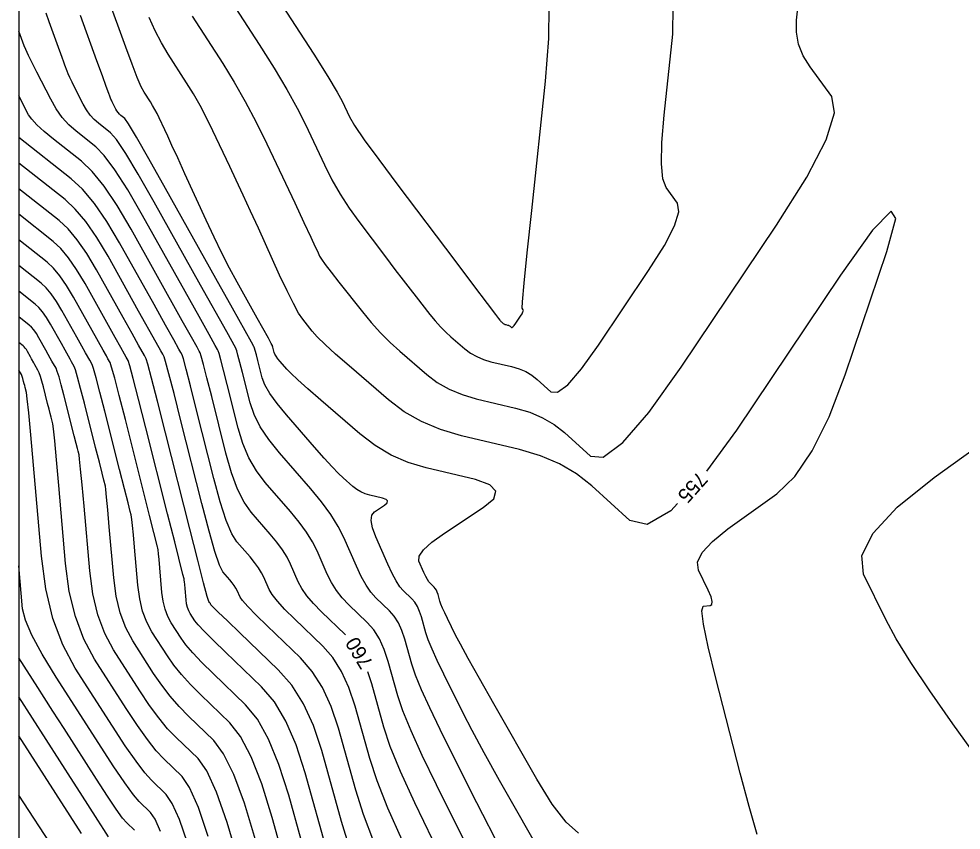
# Model space of a CAD drawing. Extents: x 2082232 to 2083549, y 592624 to 593832.
# Drawn here: x 2082231.79 to 2082277.24, y 593503.2 to 593542.34 of the extents above; entities that cross this region are included whole.
import ezdxf

# ---------------------------------------------------------------- set-up
doc = ezdxf.new("R2010")
doc.units = 0
for name, color, linetype in [('DT_X_Contour_Major', 7, 'Continuous'), ('DT_X_Contour_Minor', 7, 'Continuous'), ('DT_X_TIN_Hull', 7, 'Continuous')]:
    doc.layers.add(name, color=color, linetype=linetype)

msp = doc.modelspace()

# ---------------------------------------------------------------- linework, layer by layer
at = {"layer": 'DT_X_Contour_Major'}
for points in [[(2082263.563, 593518.955), (2082263.232, 593518.606), (2082262.096, 593517.946), (2082261.258, 593518.142), (2082259.42, 593519.808), (2082258.685, 593520.386), (2082257.861, 593520.87), (2082256.945, 593521.26), (2082255.94, 593521.556), (2082253.138, 593522.222), (2082252.129, 593522.518), (2082251.205, 593522.905), (2082250.366, 593523.383), (2082249.611, 593523.954), (2082247.711, 593525.597), (2082247.066, 593526.163), (2082246.556, 593526.63), (2082246.181, 593526.997), (2082245.941, 593527.265), (2082245.481, 593527.848), (2082245.282, 593528.145), (2082245.029, 593528.599), (2082244.724, 593529.21), (2082244.365, 593529.978), (2082243.338, 593532.235), (2082242.963, 593533.057), (2082242.609, 593533.827), (2082242.275, 593534.547), (2082241.961, 593535.216), (2082241.151, 593536.933), (2082240.844, 593537.561), (2082240.529, 593538.157), (2082240.207, 593538.722), (2082239.876, 593539.254), (2082238.986, 593540.633), (2082238.662, 593541.173), (2082238.357, 593541.762), (2082238.072, 593542.398)], [(2082247.544, 593512.615), (2082247.519, 593512.643), (2082246.388, 593513.73), (2082246, 593514.126), (2082245.682, 593514.501), (2082245.436, 593514.853), (2082245.261, 593515.183), (2082244.888, 593516.034), (2082244.722, 593516.363), (2082244.505, 593516.712), (2082244.235, 593517.082), (2082243.914, 593517.471), (2082242.989, 593518.536), (2082242.653, 593519.014), (2082242.339, 593519.647), (2082242.047, 593520.436), (2082241.778, 593521.382), (2082241.088, 593524.11), (2082240.859, 593525.01), (2082240.691, 593525.661), (2082240.582, 593526.065), (2082240.534, 593526.221), (2082240.487, 593526.306), (2082240.384, 593526.49), (2082240.112, 593526.977), (2082239.669, 593527.769), (2082237.199, 593532.19), (2082236.527, 593533.33), (2082235.903, 593534.258), (2082235.328, 593534.973), (2082234.801, 593535.475), (2082233.462, 593536.531), (2082233.01, 593536.902), (2082232.658, 593537.222), (2082232.407, 593537.493), (2082232.256, 593537.713), (2082231.787, 593538.625)], [(2082267.402, 593502.988), (2082267.006, 593504.338), (2082266.581, 593505.938), (2082265.409, 593510.536), (2082265.041, 593512.045), (2082264.814, 593513.127), (2082264.729, 593513.781), (2082264.787, 593514.006), (2082265.129, 593514.035), (2082265.219, 593514.089), (2082265.234, 593514.231), (2082265.172, 593514.459), (2082265.035, 593514.775), (2082264.569, 593515.731), (2082264.527, 593516.125), (2082264.75, 593516.589), (2082265.237, 593517.122), (2082265.99, 593517.725), (2082268.351, 593519.427), (2082269.221, 593520.264), (2082270.058, 593521.498), (2082270.863, 593523.131), (2082271.637, 593525.161), (2082273.657, 593531.106), (2082274.085, 593532.707), (2082273.853, 593533.05), (2082272.962, 593532.135), (2082271.412, 593529.963), (2082266.398, 593522.495), (2082264.957, 593520.521)], [(2082246.003, 593500.579), (2082244.802, 593504.885), (2082244.334, 593506.369), (2082243.832, 593507.59), (2082243.295, 593508.549), (2082242.724, 593509.246), (2082241.155, 593510.754), (2082240.617, 593511.284), (2082240.181, 593511.744), (2082239.847, 593512.133), (2082239.615, 593512.451), (2082239.132, 593513.206), (2082238.968, 593513.509), (2082238.84, 593513.853), (2082238.748, 593514.238), (2082238.691, 593514.663), (2082238.587, 593515.852), (2082238.552, 593516.246), (2082238.525, 593516.534), (2082238.506, 593516.717), (2082238.496, 593516.796), (2082238.478, 593516.864), (2082238.303, 593517.556), (2082238.095, 593518.381), (2082237.805, 593519.527), (2082236.925, 593523.008), (2082236.631, 593524.159), (2082236.41, 593525), (2082236.262, 593525.533), (2082236.187, 593525.757), (2082236.084, 593525.941), (2082236.008, 593526.077), (2082235.857, 593526.348), (2082235.328, 593527.294), (2082234.423, 593528.914), (2082234.089, 593529.474), (2082233.767, 593529.94), (2082233.456, 593530.313), (2082233.157, 593530.591), (2082231.787, 593531.671)], [(2082239.917, 593502.584), (2082239.529, 593503.709), (2082239.189, 593504.487), (2082238.897, 593504.919), (2082238.18, 593505.608), (2082237.861, 593505.965), (2082237.441, 593506.519), (2082236.921, 593507.271), (2082236.3, 593508.22), (2082234.51, 593511.014), (2082233.905, 593512.137), (2082233.431, 593513.411), (2082233.089, 593514.835), (2082232.879, 593516.41), (2082232.493, 593520.811), (2082232.363, 593522.267), (2082232.264, 593523.334), (2082232.195, 593524.012), (2082232.155, 593524.302), (2082232.091, 593524.556), (2082232.068, 593524.646), (2082232.049, 593524.724), (2082232.017, 593524.847), (2082231.984, 593524.981), (2082231.969, 593525.03), (2082231.952, 593525.079), (2082231.931, 593525.126), (2082231.907, 593525.173), (2082231.787, 593525.387)], [(2082251.757, 593502.716), (2082250.885, 593504.512), (2082250.2, 593506.019), (2082249.701, 593507.238), (2082249.389, 593508.167), (2082248.805, 593510.259), (2082248.616, 593510.83)], [(2082233.514, 593502.253), (2082231.787, 593504.889)]]:
    msp.add_lwpolyline(points, dxfattribs=at)
at = {"layer": 'DT_X_Contour_Minor'}
for points in [[(2082242.453, 593546.143), (2082245.118, 593542.018), (2082246.009, 593540.63), (2082246.683, 593539.557), (2082247.141, 593538.802), (2082247.382, 593538.362), (2082247.735, 593537.612), (2082247.98, 593537.195), (2082248.45, 593536.507), (2082249.145, 593535.547), (2082250.065, 593534.316), (2082252.817, 593530.672), (2082253.723, 593529.472), (2082254.377, 593528.606), (2082254.778, 593528.075), (2082254.928, 593527.878), (2082254.992, 593527.797), (2082255.015, 593527.769), (2082255.039, 593527.742), (2082255.063, 593527.718), (2082255.087, 593527.696), (2082255.151, 593527.641), (2082255.176, 593527.622), (2082255.204, 593527.606), (2082255.235, 593527.593), (2082255.269, 593527.583), (2082255.363, 593527.56), (2082255.397, 593527.551), (2082255.427, 593527.537), (2082255.455, 593527.521), (2082255.479, 593527.502), (2082255.541, 593527.446), (2082255.572, 593527.444), (2082255.618, 593527.478), (2082255.68, 593527.55), (2082255.758, 593527.658), (2082255.985, 593527.997), (2082256.057, 593528.111), (2082256.103, 593528.2), (2082256.123, 593528.265), (2082256.117, 593528.304), (2082256.065, 593528.374), (2082256.079, 593528.689), (2082256.16, 593529.581), (2082256.309, 593531.051), (2082256.524, 593533.097), (2082257.187, 593539.323), (2082257.355, 593541.393), (2082257.361, 593542.933)], [(2082241.298, 593544.307), (2082243.371, 593541.097), (2082244.094, 593539.953), (2082244.709, 593538.927), (2082245.215, 593538.021), (2082245.613, 593537.233), (2082246.529, 593535.291), (2082246.889, 593534.573), (2082247.285, 593533.878), (2082247.716, 593533.205), (2082248.182, 593532.554), (2082249.471, 593530.847), (2082249.925, 593530.247), (2082250.322, 593529.727), (2082250.661, 593529.287), (2082250.943, 593528.927), (2082251.616, 593528.074), (2082251.869, 593527.767), (2082252.122, 593527.485), (2082252.375, 593527.228), (2082252.628, 593526.996), (2082253.304, 593526.412), (2082253.573, 593526.209), (2082253.871, 593526.039), (2082254.2, 593525.901), (2082254.558, 593525.796), (2082255.555, 593525.559), (2082255.913, 593525.454), (2082256.238, 593525.315), (2082256.532, 593525.143), (2082256.793, 593524.937), (2082257.447, 593524.345), (2082257.774, 593524.319), (2082258.267, 593524.685), (2082258.924, 593525.444), (2082259.746, 593526.595), (2082262.158, 593530.188), (2082262.924, 593531.402), (2082263.413, 593532.35), (2082263.623, 593533.031), (2082263.557, 593533.445), (2082263.009, 593534.195), (2082262.849, 593534.624), (2082262.779, 593535.349), (2082262.799, 593536.371), (2082262.91, 593537.688), (2082263.326, 593541.595), (2082263.345, 593542.941)], [(2082240.142, 593542.47), (2082241.624, 593540.176), (2082242.173, 593539.289), (2082242.71, 593538.35), (2082243.234, 593537.357), (2082243.745, 593536.312), (2082245.092, 593533.455), (2082245.54, 593532.507), (2082245.871, 593531.803), (2082246.086, 593531.345), (2082246.185, 593531.132), (2082246.294, 593530.892), (2082246.383, 593530.746), (2082246.568, 593530.488), (2082246.848, 593530.119), (2082247.224, 593529.638), (2082248.355, 593528.206), (2082248.787, 593527.683), (2082249.233, 593527.191), (2082249.694, 593526.729), (2082250.169, 593526.296), (2082251.458, 593525.183), (2082251.969, 593524.796), (2082252.538, 593524.472), (2082253.164, 593524.209), (2082253.848, 593524.009), (2082255.747, 593523.558), (2082256.429, 593523.357), (2082257.049, 593523.092), (2082257.609, 593522.764), (2082258.106, 593522.373), (2082259.353, 593521.244), (2082259.977, 593521.194), (2082260.915, 593521.892), (2082262.168, 593523.339), (2082263.735, 593525.532), (2082268.332, 593532.38), (2082269.791, 593534.694), (2082270.722, 593536.499), (2082271.124, 593537.797), (2082270.997, 593538.587), (2082269.953, 593540.016), (2082269.618, 593540.559), (2082269.397, 593541.118), (2082269.29, 593541.691), (2082269.297, 593542.279), (2082269.466, 593543.867)], [(2082258.787, 593503.051), (2082258.179, 593503.589), (2082257.505, 593504.457), (2082256.764, 593505.655), (2082254.7, 593509.287), (2082254.004, 593510.516), (2082253.465, 593511.479), (2082253.082, 593512.176), (2082252.855, 593512.607), (2082252.461, 593513.401), (2082252.327, 593513.676), (2082252.222, 593513.907), (2082252.145, 593514.094), (2082252.097, 593514.237), (2082252.008, 593514.558), (2082251.97, 593514.671), (2082251.925, 593514.77), (2082251.872, 593514.854), (2082251.811, 593514.924), (2082251.637, 593515.09), (2082251.569, 593515.171), (2082251.494, 593515.287), (2082251.413, 593515.44), (2082251.326, 593515.628), (2082251.085, 593516.178), (2082251.094, 593516.417), (2082251.302, 593516.72), (2082251.708, 593517.087), (2082252.313, 593517.518), (2082254.19, 593518.755), (2082254.695, 593519.187), (2082254.8, 593519.556), (2082254.506, 593519.862), (2082253.813, 593520.106), (2082251.434, 593520.671), (2082250.565, 593520.933), (2082249.743, 593521.294), (2082248.967, 593521.755), (2082248.239, 593522.314), (2082246.36, 593523.939), (2082245.728, 593524.489), (2082245.242, 593524.923), (2082244.902, 593525.238), (2082244.708, 593525.437), (2082244.384, 593525.81), (2082244.275, 593525.942), (2082244.192, 593526.057), (2082244.135, 593526.156), (2082244.103, 593526.239), (2082244.053, 593526.438), (2082244.036, 593526.504), (2082244.024, 593526.551), (2082244.016, 593526.581), (2082244.012, 593526.592), (2082244.009, 593526.598), (2082243.962, 593526.681), (2082243.825, 593526.927), (2082243.28, 593527.903), (2082242.311, 593529.636), (2082241.946, 593530.31), (2082241.575, 593531.031), (2082241.2, 593531.801), (2082240.819, 593532.618), (2082239.799, 593534.862), (2082239.451, 593535.625), (2082239.173, 593536.232), (2082238.966, 593536.683), (2082238.829, 593536.977), (2082238.557, 593537.554), (2082238.454, 593537.764), (2082238.348, 593537.965), (2082238.24, 593538.154), (2082238.129, 593538.333), (2082237.83, 593538.796), (2082237.691, 593539.062), (2082237.496, 593539.514), (2082237.247, 593540.152), (2082236.942, 593540.976), (2082236.057, 593543.42)], [(2082254.768, 593502.796), (2082254.165, 593503.944), (2082253.593, 593505.073), (2082252.109, 593508.058), (2082251.606, 593509.094), (2082251.211, 593509.963), (2082250.923, 593510.666), (2082250.743, 593511.202), (2082250.406, 593512.408), (2082250.265, 593512.834), (2082250.095, 593513.205), (2082249.895, 593513.521), (2082249.665, 593513.783), (2082249.013, 593514.41), (2082248.77, 593514.681), (2082248.532, 593515.023), (2082248.297, 593515.438), (2082248.066, 593515.924), (2082247.457, 593517.315), (2082247.186, 593517.853), (2082246.83, 593518.424), (2082246.39, 593519.028), (2082245.865, 593519.665), (2082244.352, 593521.406), (2082243.839, 593522.046), (2082243.432, 593522.66), (2082243.133, 593523.248), (2082242.94, 593523.81), (2082242.57, 593525.274), (2082242.447, 593525.757), (2082242.357, 593526.106), (2082242.299, 593526.323), (2082242.273, 593526.406), (2082242.248, 593526.452), (2082241.813, 593527.229), (2082240.549, 593529.492), (2082238.309, 593533.5), (2082237.548, 593534.836), (2082236.942, 593535.839), (2082236.493, 593536.508), (2082236.2, 593536.844), (2082235.628, 593537.296), (2082235.421, 593537.48), (2082235.23, 593537.696), (2082235.055, 593537.943), (2082234.896, 593538.221), (2082234.493, 593539.004), (2082234.356, 593539.274), (2082234.247, 593539.499), (2082234.165, 593539.678), (2082234.112, 593539.811), (2082234.005, 593540.104), (2082233.952, 593540.251), (2082233.873, 593540.47), (2082233.635, 593541.125), (2082233.249, 593542.193), (2082233.1, 593542.612)], [(2082258.456, 593499.457), (2082255.869, 593504.009), (2082254.976, 593505.591), (2082254.238, 593506.924), (2082253.654, 593508.007), (2082253.224, 593508.84), (2082252.285, 593510.729), (2082251.966, 593511.385), (2082251.716, 593511.935), (2082251.534, 593512.38), (2082251.42, 593512.719), (2082251.207, 593513.483), (2082251.118, 593513.752), (2082251.01, 593513.987), (2082250.883, 593514.187), (2082250.738, 593514.353), (2082250.325, 593514.75), (2082250.163, 593514.942), (2082249.985, 593515.219), (2082249.793, 593515.582), (2082249.585, 593516.03), (2082249.012, 593517.339), (2082248.846, 593517.784), (2082248.779, 593518.135), (2082248.81, 593518.393), (2082248.94, 593518.558), (2082249.419, 593518.873), (2082249.548, 593518.983), (2082249.574, 593519.077), (2082249.5, 593519.155), (2082249.323, 593519.217), (2082248.716, 593519.362), (2082248.495, 593519.428), (2082248.285, 593519.52), (2082248.088, 593519.638), (2082247.902, 593519.78), (2082247.423, 593520.194), (2082247.202, 593520.403), (2082246.9, 593520.72), (2082246.515, 593521.143), (2082246.048, 593521.674), (2082244.695, 593523.232), (2082244.24, 593523.783), (2082243.894, 593524.265), (2082243.654, 593524.679), (2082243.522, 593525.025), (2082243.311, 593525.856), (2082243.242, 593526.13), (2082243.19, 593526.329), (2082243.157, 593526.452), (2082243.143, 593526.499), (2082243.128, 593526.525), (2082243.01, 593526.737), (2082242.093, 593528.378), (2082241.295, 593529.806), (2082238.865, 593534.155), (2082238.058, 593535.589), (2082237.462, 593536.629), (2082237.076, 593537.276), (2082236.9, 593537.529), (2082236.71, 593537.678), (2082236.642, 593537.739), (2082236.579, 593537.811), (2082236.521, 593537.892), (2082236.468, 593537.984), (2082236.335, 593538.243), (2082236.29, 593538.333), (2082236.254, 593538.407), (2082236.227, 593538.466), (2082236.209, 593538.51), (2082236.174, 593538.607), (2082236.125, 593538.741), (2082236.006, 593539.07), (2082235.816, 593539.594), (2082235.556, 593540.313), (2082234.767, 593542.491)], [(2082253.962, 593501.307), (2082251.933, 593505.387), (2082251.245, 593506.803), (2082250.705, 593507.991), (2082250.312, 593508.952), (2082250.066, 593509.684), (2082249.606, 593511.334), (2082249.413, 593511.915), (2082249.18, 593512.422), (2082248.906, 593512.855), (2082248.592, 593513.213), (2082247.7, 593514.07), (2082247.385, 593514.404), (2082247.107, 593514.762), (2082246.866, 593515.145), (2082246.663, 593515.553), (2082246.172, 593516.675), (2082245.954, 593517.108), (2082245.668, 593517.568), (2082245.313, 593518.055), (2082244.89, 593518.568), (2082243.671, 593519.971), (2082243.246, 593520.53), (2082242.886, 593521.154), (2082242.59, 593521.842), (2082242.359, 593522.596), (2082241.829, 593524.692), (2082241.653, 593525.383), (2082241.524, 593525.884), (2082241.441, 593526.194), (2082241.404, 593526.314), (2082241.367, 593526.379), (2082241.259, 593526.572), (2082240.962, 593527.103), (2082240.477, 593527.972), (2082239.803, 593529.178), (2082237.754, 593532.845), (2082237.037, 593534.083), (2082236.423, 593535.048), (2082235.91, 593535.741), (2082235.501, 593536.16), (2082234.545, 593536.913), (2082234.199, 593537.222), (2082233.881, 593537.582), (2082233.589, 593537.994), (2082233.323, 593538.458), (2082232.651, 593539.764), (2082232.424, 593540.211), (2082232.246, 593540.573), (2082232.118, 593540.85), (2082232.039, 593541.042), (2082231.787, 593541.739)], [(2082250.281, 593502.711), (2082249.586, 593504.265), (2082249.063, 593505.578), (2082248.712, 593506.649), (2082248.004, 593509.184), (2082247.708, 593510.078), (2082247.35, 593510.857), (2082246.929, 593511.522), (2082246.446, 593512.073), (2082245.076, 593513.39), (2082244.615, 593513.849), (2082244.258, 593514.239), (2082244.005, 593514.561), (2082243.858, 593514.813), (2082243.603, 593515.394), (2082243.49, 593515.618), (2082243.342, 593515.857), (2082243.158, 593516.109), (2082242.939, 593516.374), (2082242.307, 593517.101), (2082242.06, 593517.497), (2082241.793, 593518.14), (2082241.505, 593519.03), (2082241.196, 593520.167), (2082240.346, 593523.528), (2082240.065, 593524.636), (2082239.857, 593525.439), (2082239.724, 593525.936), (2082239.665, 593526.128), (2082239.606, 593526.233), (2082239.509, 593526.407), (2082239.261, 593526.852), (2082238.861, 593527.566), (2082238.312, 593528.55), (2082236.644, 593531.534), (2082236.029, 593532.567), (2082235.435, 593533.426), (2082234.863, 593534.112), (2082234.311, 593534.625), (2082231.787, 593536.615)], [(2082248.915, 593502.625), (2082248.41, 593503.947), (2082248.034, 593505.132), (2082247.204, 593508.11), (2082246.856, 593509.159), (2082246.435, 593510.075), (2082245.941, 593510.856), (2082245.374, 593511.503), (2082243.764, 593513.05), (2082243.229, 593513.572), (2082242.833, 593513.978), (2082242.575, 593514.268), (2082242.455, 593514.443), (2082242.319, 593514.753), (2082242.258, 593514.873), (2082242.179, 593515.001), (2082242.081, 593515.135), (2082241.963, 593515.278), (2082241.626, 593515.666), (2082241.468, 593515.981), (2082241.246, 593516.634), (2082240.962, 593517.624), (2082240.615, 593518.953), (2082239.605, 593522.946), (2082239.271, 593524.263), (2082239.024, 593525.216), (2082238.866, 593525.807), (2082238.795, 593526.035), (2082238.726, 593526.16), (2082238.634, 593526.325), (2082238.41, 593526.726), (2082237.566, 593528.236), (2082236.089, 593530.879), (2082235.544, 593531.794), (2082235.018, 593532.555), (2082234.511, 593533.162), (2082234.023, 593533.617), (2082231.787, 593535.379)], [(2082247.758, 593502.316), (2082247.357, 593503.614), (2082246.403, 593507.035), (2082246.003, 593508.241), (2082245.52, 593509.292), (2082244.952, 593510.19), (2082244.301, 593510.933), (2082242.452, 593512.71), (2082241.844, 593513.294), (2082241.408, 593513.716), (2082241.144, 593513.976), (2082241.052, 593514.072), (2082241.034, 593514.113), (2082241.026, 593514.128), (2082241.016, 593514.145), (2082241.003, 593514.162), (2082240.988, 593514.181), (2082240.944, 593514.231), (2082240.875, 593514.465), (2082240.7, 593515.127), (2082240.42, 593516.218), (2082240.034, 593517.739), (2082238.864, 593522.364), (2082238.476, 593523.889), (2082238.191, 593524.994), (2082238.007, 593525.678), (2082237.926, 593525.942), (2082237.845, 593526.087), (2082237.559, 593526.6), (2082237.246, 593527.16), (2082236.82, 593527.922), (2082235.534, 593530.224), (2082235.059, 593531.02), (2082234.601, 593531.683), (2082234.16, 593532.213), (2082233.734, 593532.608), (2082231.787, 593534.143)], [(2082246.68, 593502.097), (2082245.602, 593505.96), (2082245.167, 593507.306), (2082244.67, 593508.447), (2082244.111, 593509.382), (2082243.489, 593510.112), (2082241.75, 593511.783), (2082241.168, 593512.348), (2082240.729, 593512.789), (2082240.433, 593513.105), (2082240.278, 593513.297), (2082240.056, 593513.644), (2082239.981, 593513.784), (2082239.922, 593513.942), (2082239.88, 593514.119), (2082239.853, 593514.314), (2082239.805, 593514.861), (2082239.789, 593515.042), (2082239.777, 593515.174), (2082239.768, 593515.258), (2082239.764, 593515.294), (2082239.756, 593515.326), (2082239.704, 593515.531), (2082239.307, 593517.099), (2082238.962, 593518.463), (2082237.913, 593522.613), (2082237.564, 593523.983), (2082237.305, 593524.979), (2082237.136, 593525.601), (2082237.057, 593525.85), (2082236.965, 593526.014), (2082236.883, 593526.16), (2082236.708, 593526.474), (2082236.438, 593526.957), (2082234.978, 593529.569), (2082234.574, 593530.247), (2082234.184, 593530.812), (2082233.808, 593531.263), (2082233.446, 593531.6), (2082231.787, 593532.907)], [(2082245.326, 593499.062), (2082244.001, 593503.811), (2082243.501, 593505.432), (2082242.994, 593506.734), (2082242.48, 593507.717), (2082241.958, 593508.381), (2082240.56, 593509.725), (2082240.066, 593510.22), (2082239.633, 593510.699), (2082239.262, 593511.16), (2082238.952, 593511.605), (2082238.207, 593512.767), (2082237.956, 593513.235), (2082237.758, 593513.765), (2082237.616, 593514.357), (2082237.528, 593515.013), (2082237.368, 593516.844), (2082237.314, 593517.45), (2082237.273, 593517.894), (2082237.244, 593518.176), (2082237.227, 593518.297), (2082237.201, 593518.403), (2082237.159, 593518.569), (2082237.052, 593518.989), (2082236.882, 593519.663), (2082236.647, 593520.591), (2082235.936, 593523.402), (2082235.698, 593524.334), (2082235.515, 593525.022), (2082235.388, 593525.465), (2082235.318, 593525.664), (2082235.204, 593525.868), (2082235.006, 593526.222), (2082234.822, 593526.551), (2082234.582, 593526.98), (2082233.868, 593528.258), (2082233.605, 593528.701), (2082233.35, 593529.069), (2082233.105, 593529.363), (2082232.869, 593529.583), (2082231.787, 593530.435)], [(2082243.2, 593502.736), (2082242.668, 593504.495), (2082242.155, 593505.878), (2082241.664, 593506.885), (2082241.193, 593507.515), (2082239.965, 593508.695), (2082239.514, 593509.156), (2082239.085, 593509.654), (2082238.677, 593510.188), (2082238.289, 593510.758), (2082237.283, 593512.329), (2082236.943, 593512.96), (2082236.677, 593513.676), (2082236.484, 593514.477), (2082236.366, 593515.362), (2082236.149, 593517.836), (2082236.076, 593518.654), (2082236.02, 593519.254), (2082235.981, 593519.635), (2082235.959, 593519.798), (2082235.886, 593520.088), (2082235.801, 593520.423), (2082235.669, 593520.945), (2082235.49, 593521.655), (2082234.948, 593523.797), (2082234.765, 593524.51), (2082234.62, 593525.044), (2082234.515, 593525.397), (2082234.448, 593525.571), (2082234.323, 593525.795), (2082234.258, 593525.912), (2082234.014, 593526.347), (2082233.837, 593526.666), (2082233.313, 593527.603), (2082233.12, 593527.927), (2082232.933, 593528.197), (2082232.753, 593528.413), (2082232.58, 593528.574), (2082231.787, 593529.199)], [(2082242.4, 593501.661), (2082241.834, 593503.558), (2082241.317, 593505.021), (2082240.848, 593506.052), (2082240.428, 593506.65), (2082239.37, 593507.666), (2082238.963, 593508.092), (2082238.537, 593508.609), (2082238.091, 593509.216), (2082237.626, 593509.912), (2082236.359, 593511.891), (2082235.93, 593512.686), (2082235.595, 593513.588), (2082235.353, 593514.596), (2082235.204, 593515.711), (2082234.93, 593518.827), (2082234.839, 593519.858), (2082234.768, 593520.614), (2082234.719, 593521.094), (2082234.691, 593521.299), (2082234.646, 593521.48), (2082234.613, 593521.608), (2082234.55, 593521.857), (2082234.457, 593522.227), (2082233.96, 593524.191), (2082233.832, 593524.686), (2082233.725, 593525.065), (2082233.641, 593525.329), (2082233.579, 593525.478), (2082233.383, 593525.829), (2082233.304, 593525.97), (2082233.207, 593526.144), (2082233.091, 593526.351), (2082232.758, 593526.948), (2082232.635, 593527.154), (2082232.516, 593527.326), (2082232.402, 593527.463), (2082232.291, 593527.566), (2082231.787, 593527.963)], [(2082240.925, 593502.895), (2082240.445, 593504.287), (2082240.024, 593505.25), (2082239.662, 593505.784), (2082238.775, 593506.637), (2082238.412, 593507.029), (2082237.989, 593507.564), (2082237.506, 593508.243), (2082236.963, 593509.066), (2082235.434, 593511.452), (2082234.918, 593512.411), (2082234.513, 593513.499), (2082234.221, 593514.716), (2082234.041, 593516.061), (2082233.712, 593519.819), (2082233.601, 593521.062), (2082233.516, 593521.974), (2082233.457, 593522.553), (2082233.423, 593522.801), (2082233.341, 593523.127), (2082233.299, 593523.291), (2082233.244, 593523.509), (2082233.175, 593523.783), (2082232.972, 593524.586), (2082232.898, 593524.862), (2082232.83, 593525.087), (2082232.767, 593525.262), (2082232.709, 593525.385), (2082232.562, 593525.649), (2082232.507, 593525.747), (2082232.399, 593525.941), (2082232.345, 593526.037), (2082232.202, 593526.293), (2082232.15, 593526.381), (2082232.099, 593526.455), (2082232.05, 593526.513), (2082232.003, 593526.557), (2082231.787, 593526.727)], [(2082280.101, 593503.79), (2082276.842, 593508.323), (2082275.722, 593509.912), (2082274.809, 593511.282), (2082274.101, 593512.431), (2082273.599, 593513.361), (2082272.534, 593515.545), (2082272.447, 593516.451), (2082272.986, 593517.531), (2082274.149, 593518.785), (2082275.938, 593520.213), (2082281.542, 593524.251)], [(2082238.613, 593503.131), (2082238.354, 593503.724), (2082238.131, 593504.053), (2082237.585, 593504.578), (2082237.309, 593504.901), (2082236.893, 593505.474), (2082236.335, 593506.298), (2082235.637, 593507.374), (2082233.586, 593510.576), (2082232.908, 593511.682), (2082232.413, 593512.6), (2082232.1, 593513.329), (2082231.97, 593513.87), (2082231.787, 593515.952)], [(2082237.366, 593503.188), (2082236.99, 593503.549), (2082236.793, 593503.782), (2082236.484, 593504.211), (2082236.064, 593504.835), (2082235.533, 593505.655), (2082233.966, 593508.101), (2082233.433, 593508.933), (2082233.009, 593509.594), (2082232.695, 593510.085), (2082231.787, 593511.503)], [(2082236.118, 593502.882), (2082235.889, 593503.223), (2082235.598, 593503.671), (2082234.742, 593505.008), (2082234.417, 593505.514), (2082231.787, 593509.621)], [(2082234.804, 593503.03), (2082231.787, 593507.74)]]:
    msp.add_lwpolyline(points, dxfattribs=at)
at = {"layer": 'DT_X_TIN_Hull'}
msp.add_lwpolyline([(2082231.787, 593570.568), (2082231.787, 593561.964), (2082231.787, 593559.177), (2082231.787, 593552.664), (2082231.787, 593549.199), (2082231.787, 593541.907), (2082231.787, 593540.947), (2082231.787, 593537.246), (2082231.787, 593525.802), (2082231.787, 593525.059), (2082231.787, 593524.598), (2082231.787, 593512.946), (2082231.787, 593507.594), (2082231.787, 593500.854)], dxfattribs=at)

# ---------------------------------------------------------------- texts
at = {"layer": 'DT_X_Contour_Major'}
for s, rotation, p in [('755', 228.3133, (2082264.549, 593520.542)), ('760', 120.9887, (2082248.901, 593511.252))]:
    msp.add_text(s, height=0.7, rotation=rotation, dxfattribs=at).set_placement(p)

doc.saveas('drawing.dxf')
